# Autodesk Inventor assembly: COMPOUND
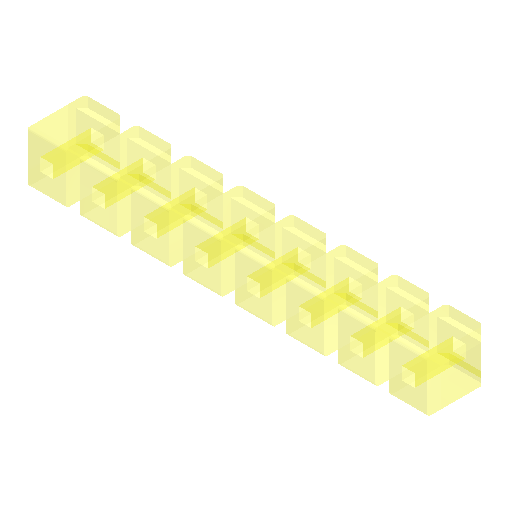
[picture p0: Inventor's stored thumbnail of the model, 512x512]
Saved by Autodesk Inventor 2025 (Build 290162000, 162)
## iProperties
Created: 2025-05
Part Number: COMPOUND
Document SubType Name: Assembly
Designer: R5800u
Author: R5800u
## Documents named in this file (9)
- C:\Users\R5800u\Desktop\drone\c3\ESP32-C3 Super Mini breakout expansion board module -Assembly\COMPOUND_1.iam
- C:\Users\R5800u\Desktop\drone\c3\ESP32-C3 Super Mini breakout expansion board module -Assembly\COMPOUND_8.ipt
- C:\Users\R5800u\Desktop\drone\c3\ESP32-C3 Super Mini breakout expansion board module -Assembly\COMPOUND_9.ipt
- C:\Users\R5800u\Desktop\drone\c3\ESP32-C3 Super Mini breakout expansion board module -Assembly\COMPOUND_10.ipt
- C:\Users\R5800u\Desktop\drone\c3\ESP32-C3 Super Mini breakout expansion board module -Assembly\COMPOUND_11.ipt
- C:\Users\R5800u\Desktop\drone\c3\ESP32-C3 Super Mini breakout expansion board module -Assembly\COMPOUND_12.ipt
- C:\Users\R5800u\Desktop\drone\c3\ESP32-C3 Super Mini breakout expansion board module -Assembly\COMPOUND_13.ipt
- C:\Users\R5800u\Desktop\drone\c3\ESP32-C3 Super Mini breakout expansion board module -Assembly\COMPOUND_14.ipt
- C:\Users\R5800u\Desktop\drone\c3\ESP32-C3 Super Mini breakout expansion board module -Assembly\COMPOUND_15.ipt
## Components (8 placed, 8 different names)
1. 11
2. 12
3. 13
4. 14
5. 15
6. 16
7. 17
8. 18
